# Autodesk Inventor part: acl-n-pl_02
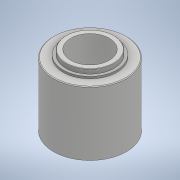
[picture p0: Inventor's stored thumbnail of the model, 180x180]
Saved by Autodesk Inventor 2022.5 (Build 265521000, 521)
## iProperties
Part Number: acl-n-pl_02
Material: 一般
Document SubType Name: Modeling
Designer: ImaoCorp
Density: 1 g/cm^3
Appearance: 既定
Author: ImaoCorp
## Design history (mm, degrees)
feature "acl-n-pl_02"
node "ソリッド1"
